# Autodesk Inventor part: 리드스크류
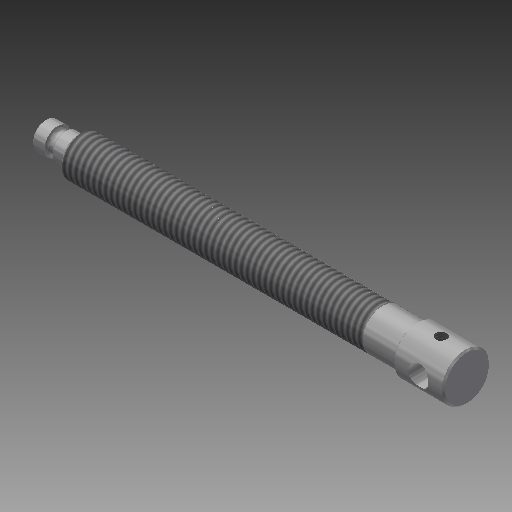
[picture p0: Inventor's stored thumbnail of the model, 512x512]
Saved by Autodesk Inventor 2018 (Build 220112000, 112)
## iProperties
Created: 2019-04
Part Number: 리드스크류
Material: 강철, 연강
Document SubType Name: Modeling
Designer: mduedu
Density: 1 g/cm^3
Appearance: Steel
Author: mduedu
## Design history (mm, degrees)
sketch "스케치1"
  geometry: C1 r 6 at (0, 0); 1 further point
  constraints: 1 centre point, 1 coincident
  dimensions: "d0" = 12 diameter of C1
extrude "돌출1" new body sketch "스케치1" distance "d1" = 100; taper "d2" = 0 deg
sketch "스케치2"
  geometry: C1 r 4 at (0, 0); 1 further point
  constraints: 1 centre point, 1 coincident
  dimensions: "d3" = 8 diameter of C1
extrude "돌출2" join sketch "스케치2" distance "d4" = 10; taper "d5" = 0 deg
sketch "스케치3"
  geometry: C1 r 7 at (0, 0); 1 further point
  constraints: 1 centre point, 1 coincident
  dimensions: "d9" = 14 diameter of C1
extrude "돌출3" join sketch "스케치3" distance "d10" = 15; taper "d11" = 0 deg
feature "스레드1" dims "d12" = 90, "d13" = 0
chamfer "모따기2" distance "d14" = 1; stored, may be unused: second distance "d15" = 2, angle "d16" = 45 deg
chamfer "모따기3" distance "d17" = 0.5; stored, may be unused: second distance "d18" = 2, angle "d19" = 45 deg
chamfer "모따기4" distance "d20" = 0.5; stored, may be unused: second distance "d21" = 2, angle "d22" = 45 deg
sketch "스케치4"
  geometry: L1 (-100, -5)-(-100, 5) reference; L2 (-109.5, 4)-(-109.5, -4) reference; L3 (-109.5, 0)-(-100, 0); C1 r 1.25 at (-105, 4); 1 further point
  constraints: 2 end point, 2 midpoint, 1 centre point
  dimensions: "d23" = 2.5 diameter of C1; "d24" = 5 distance from line of C1.centre L1; "d25" = 4 distance from line of C1.centre L3
revolve "회전1" sketch "스케치4" stored, may be unused: angle "d26" = 90 deg
sketch "스케치5"
  geometry: L1 (0, -6.5)-(0, 6.5) reference; C1 r 3 at (7.5, 0); 2 further points
  constraints: 1 centre point, 1 horizontal alignment, 1 midpoint
  dimensions: "d27" = 6 diameter of C1; "d28" = 7.5 distance from line of C1.centre L1
extrude "돌출4" cut sketch "스케치5" extent not by distance; stored distance "d29" = 15; taper "d30" = 0 deg
node "작업 평면1"
sketch "스케치6"
  geometry: L1 (0, 6.5)-(0, -6.5) reference; 2 further points
  constraints: 1 horizontal alignment
  dimensions: "d31" = 7.5 distance from line of point (-7.5, 0) L1
hole "구멍1" sketch "스케치6" at (-7.5, 0) diameter "d32" = 3.242; stored, may be unused: countersink angle "d36" = 90 deg, drill point angle "d38" = 118 deg; dims "d33" = 6, "d34" = 4, "d35" = 2, "d37" = 8
node "솔리드1"
